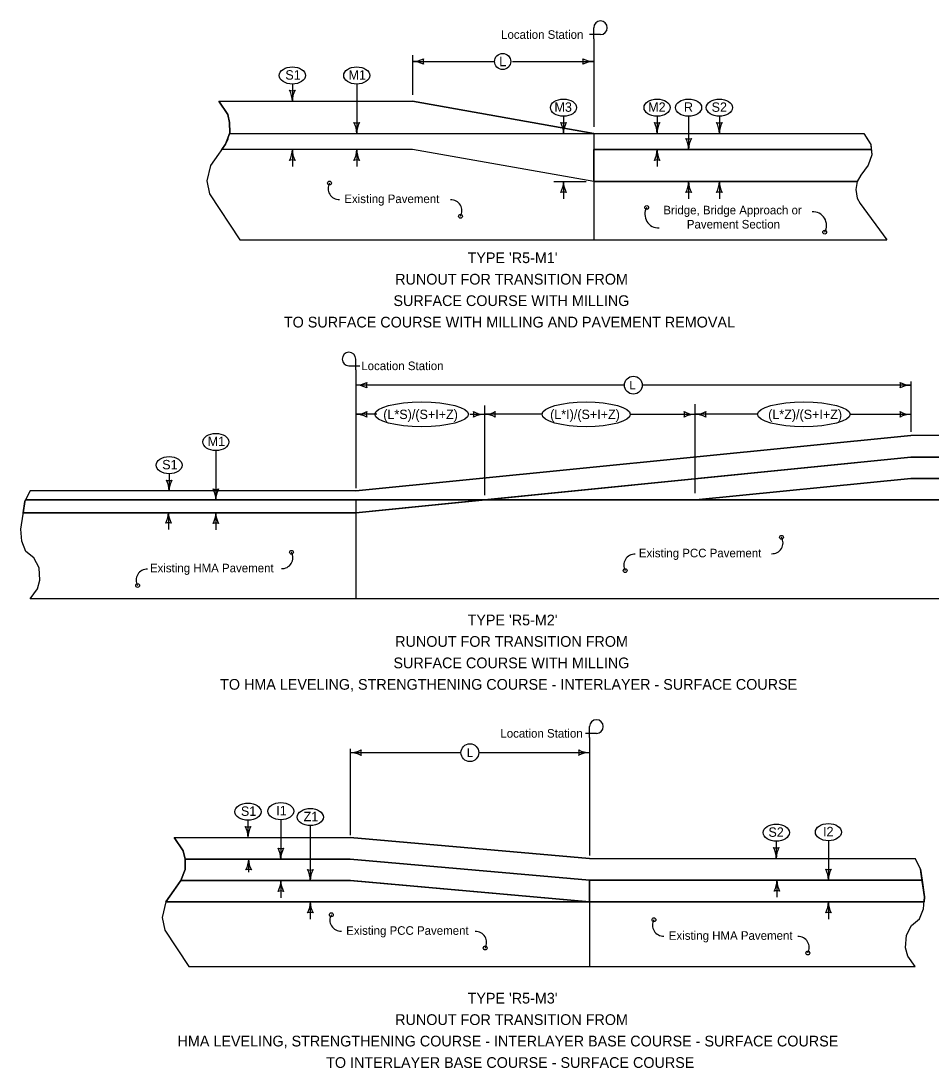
# Model space of a CAD drawing. Extents: x 10133 to 81668, y 2218 to 11018.
# Drawn here: x 10479 to 12176, y 5463 to 7415 of the extents above; entities that cross this region are included whole.
import ezdxf

# ---------------------------------------------------------------- set-up
doc = ezdxf.new("R2010")
doc.units = 0
for name, color, linetype in [('Default', 7, 'Continuous'), ('dsnNonPlotable', 7, 'Continuous'), ('dsnShtPlotShapeBatchPrint', 7, 'Continuous'), ('dsnStdBlock', 7, 'Continuous'), ('dsnStdBlockNotModified', 7, 'Continuous'), ('Level 2', 7, 'Continuous')]:
    doc.layers.add(name, color=color, linetype=linetype)

msp = doc.modelspace()

# ---------------------------------------------------------------- linework, layer by layer
at = {"layer": 'Default'}
for points in [[(10496.6, 6337.9), (10510.3, 6356.8), (10514.4, 6372.6), (10513, 6395.9), (10503.3, 6414.2), (10488.6, 6426.4), (10480.9, 6445.4), (10479.3, 6467.8), (10483.4, 6496), (10486.7, 6519.2), (10496.6, 6539.1)], [(12146.5, 5652.8), (12132.9, 5671.8), (12128.7, 5687.5), (12130.1, 5710.9), (12139.8, 5729.1), (12154.6, 5741.4), (12162.2, 5760.3), (12163.8, 5782.7), (12159.8, 5811), (12156.5, 5834.1), (12146.5, 5854.1)]]:
    msp.add_lwpolyline(points, dxfattribs=at)
at = {"layer": 'dsnNonPlotable'}
for points in [[(10860.9, 7185.7), (10868.7, 7206.5), (10868.4, 7225.7), (10865.1, 7241.1), (10848.4, 7265.7), (11209.6, 7265.7), (11547.1, 7205.7), (12050.8, 7205.7), (12057.2, 7195.4), (12063.6, 7185.2), (12064.6, 7175.7), (12065.6, 7165.6), (12058.6, 7146.2), (12045, 7127.7), (12038.3, 7115.7), (11547.1, 7115.7), (11209.6, 7175.7), (10853.8, 7175.7)], [(12446.5, 6601.8), (12449.8, 6617.8), (12466.5, 6642.4), (12138.6, 6642.4), (11103.6, 6539.1), (10496.6, 6539.1), (10486.7, 6519.2), (10483.7, 6498.5), (11103.6, 6498.5), (11343.4, 6522.4), (12138.6, 6601.8)], [(11343.4, 6522.4), (11737.8, 6522.4), (12138.6, 6562.4), (12454, 6562.4), (12446.2, 6583.3), (12446.5, 6601.8), (12138.6, 6601.8), (11343.4, 6522.4)], [(12242.3, 6521.8), (12482.2, 6522.4), (12467.4, 6543.7), (12454, 6562.4), (12138.6, 6562.4), (12138.6, 6562.4), (11737.8, 6522.4)], [(10781.9, 5868.2), (10765.2, 5892.8), (11093.1, 5892.8), (11539.6, 5854.1), (12146.5, 5854.1), (12156.5, 5834.1), (12159.4, 5813.4), (11539.6, 5813.4), (11093.1, 5852.8), (10785.2, 5852.8)], [(11539.6, 5813.4), (11539.6, 5772.8), (11093.5, 5812.8), (10777.7, 5812.8), (10785.5, 5833.6), (10785.2, 5852.8), (11093.1, 5852.8), (11539.6, 5813.4)], [(10749.5, 5772.8), (10764.3, 5794.1), (10777.7, 5812.8), (11093.1, 5812.8), (11539.6, 5772.8), (11539.6, 5772.8)], [(11539.6, 5813.4), (12159.4, 5813.4), (12163.8, 5782.7), (12163.1, 5772.8), (11539.6, 5772.8), (11539.6, 5813.4)]]:
    msp.add_lwpolyline(points, close=True, dxfattribs=at)
at = {"layer": 'dsnStdBlock'}
for p, q in [((11547.1, 7382.2), (11547.1, 7402.6)), ((11559.8, 7389.9), (11539.5, 7389.9)), ((11547.1, 7382.2), (11547.1, 7217.7)), ((11209.6, 7351.7), (11209.6, 7277.7)), ((11209.6, 7339.7), (11360.8, 7339.7)), ((11395.8, 7339.7), (11547.1, 7339.7)), ((10985.3, 7297.7), (10985.3, 7265.7)), ((11105.3, 7297.7), (11105.3, 7205.7)), ((10848.4, 7265.7), (11209.6, 7265.7)), ((11547.1, 7205.7), (11209.6, 7265.7)), ((11490.8, 7237.7), (11490.8, 7205.7)), ((11665.3, 7237.7), (11665.3, 7205.7)), ((11724.1, 7237.7), (11724.1, 7175.7)), ((11781.4, 7237.7), (11781.4, 7205.7)), ((10868, 7205.7), (11209.6, 7205.7)), ((11547.1, 7205.7), (11547.1, 7065.7)), ((11547.1, 7205.7), (12050.8, 7205.7)), ((11547.1, 7205.7), (11547.1, 7007.4)), ((11209.6, 7175.7), (10853.8, 7175.7)), ((10985.3, 7175.7), (10985.3, 7143.7)), ((11105.3, 7175.7), (11105.3, 7143.7)), ((11547.1, 7115.7), (11209.6, 7175.7)), ((12064.6, 7175.7), (11547.1, 7175.7)), ((11665.3, 7175.7), (11665.3, 7143.7)), ((11473.1, 7115.7), (11533.1, 7115.7)), ((11490.8, 7115.7), (11490.8, 7083.7)), ((11547.1, 7115.7), (12038.3, 7115.7)), ((11724.1, 7115.7), (11724.1, 7083.7)), ((11781.4, 7115.7), (11781.4, 7083.7)), ((10887.6, 7007.4), (12093.5, 7007.4)), ((11103.6, 6764.7), (11103.6, 6785)), ((11090.9, 6772.3), (11111.2, 6772.3)), ((11103.6, 6764.7), (11103.6, 6544.5)), ((11604.4, 6736.3), (11103.6, 6736.3)), ((12138.6, 6736.3), (11637.7, 6736.3)), ((12138.6, 6743.4), (12138.6, 6649.3)), ((11343.4, 6698.5), (11343.4, 6531.4)), ((11736, 6701.1), (11736, 6535.2)), ((11142.6, 6681.9), (11103.6, 6681.9)), ((11317.1, 6681.9), (11343.4, 6681.9)), ((11450.9, 6681.9), (11343.4, 6681.9)), ((11615.3, 6681.9), (11736, 6681.9)), ((11852.4, 6681.9), (11736, 6681.9)), ((12025, 6681.9), (12138.6, 6681.9)), ((11103.6, 6539.1), (12138.6, 6642.4)), ((12466.5, 6642.4), (12138.6, 6642.4)), ((10842.7, 6614.4), (10842.7, 6522.4)), ((11103.6, 6498.5), (12138.6, 6601.8)), ((12446.5, 6601.8), (12138.6, 6601.8)), ((10755.6, 6571.1), (10755.6, 6539.1)), ((11737.8, 6522.4), (12138.6, 6562.4)), ((12454, 6562.4), (12138.6, 6562.4)), ((12482.2, 6522.4), (10488.3, 6522.4)), ((11103.6, 6539.1), (10496.6, 6539.1)), ((11103.6, 6522.4), (11103.6, 6337.9)), ((11103.6, 6498.5), (10483.7, 6498.5)), ((10754.4, 6499.2), (10754.4, 6467.2)), ((10842.7, 6498.5), (10842.7, 6466.5)), ((12396.4, 6337.9), (10496.6, 6337.9)), ((11539.6, 6079.6), (11539.6, 6099.9)), ((11552.3, 6087.2), (11532, 6087.2)), ((11539.6, 6079.6), (11539.6, 5859.4)), ((11093.1, 6058.4), (11093.1, 5897.1)), ((11094.2, 6051.2), (11299.7, 6051.2)), ((11333, 6051.2), (11539.6, 6051.2)), ((10902.6, 5925.1), (10902.6, 5893.1)), ((10963.8, 5926.1), (10963.8, 5852.8)), ((11018.8, 5915.1), (11018.8, 5812.8)), ((10765.2, 5892.8), (11093.1, 5892.8)), ((11539.6, 5854.1), (11093.1, 5892.8)), ((11887.6, 5886.1), (11887.6, 5854.1)), ((11984.7, 5887.1), (11984.7, 5813.4)), ((10785.1, 5852.8), (11093.1, 5852.8)), ((10903.8, 5852.8), (10903.8, 5828.2)), ((11539.6, 5813.4), (11093.1, 5852.8)), ((11539.6, 5854.1), (12146.5, 5854.1)), ((10777.7, 5812.8), (11093.1, 5812.8)), ((10963.8, 5812.8), (10963.8, 5780.8)), ((11539.6, 5772.8), (11093.1, 5812.8)), ((11539.6, 5813.4), (12159.4, 5813.4)), ((11539.6, 5813.4), (11539.6, 5652.8)), ((11888.8, 5813.4), (11888.8, 5782.1)), ((10749.5, 5772.8), (12163.1, 5772.8)), ((11018.8, 5772.8), (11018.8, 5740.8)), ((11539.6, 5772.8), (11768.1, 5772.8)), ((11543.1, 5772.8), (12097.6, 5772.8)), ((11984.8, 5772.8), (11984.8, 5740.8)), ((10792.3, 5652.8), (12146.5, 5652.8))]:
    msp.add_line(p, q, dxfattribs=at)
for points in [[(10848.4, 7265.7), (10865.1, 7241.1), (10868.4, 7225.7), (10868.7, 7206.5), (10860.9, 7185.7), (10847.5, 7166.9), (10832.7, 7145.7), (10826.1, 7116.9), (10830.6, 7093), (10887.6, 7007.4)], [(10868, 7205.7), (11547.1, 7205.7), (12050.8, 7205.7), (12057.2, 7195.4), (12063.6, 7185.2), (12064.6, 7175.7), (11547.1, 7175.7), (11547.1, 7115.7), (11209.6, 7175.7), (10853.9, 7175.7), (10858.2, 7181.6), (10858.3, 7181.6)], [(12050.8, 7205.7), (12063.6, 7185.2), (12065.6, 7165.6), (12058.6, 7146.2), (12045, 7127.7), (12038.3, 7115.7), (12035.8, 7101.3), (12038.6, 7084.9), (12043.9, 7075.1), (12093.5, 7007.4)], [(10765.2, 5892.8), (10781.9, 5868.2), (10785.2, 5852.8), (10785.5, 5833.6), (10777.7, 5812.8), (10764.3, 5794.1), (10749.5, 5772.8), (10742.8, 5744.1), (10747.4, 5720.2), (10792.3, 5652.8)]]:
    msp.add_lwpolyline(points, dxfattribs=at)
for points in [[(11547.1, 7115.7), (11547.1, 7175.7), (12064.6, 7175.7), (12065.6, 7165.6), (12058.6, 7146.2), (12045, 7127.7), (12038.3, 7115.7)], [(10486.7, 6519.2), (10488.3, 6522.4), (11343.4, 6522.4), (11103.6, 6498.5), (10483.7, 6498.5)]]:
    msp.add_lwpolyline(points, close=True, dxfattribs=at)
for centre, radius in [((11377.4, 7339.7), 15), ((11054.6, 7113.1), 3.56), ((11646, 7067.6), 3.56), ((11298.9, 7051.1), 3.56), ((11977.8, 7021.4), 3.56), ((11621.1, 6736.3), 16.6), ((11897.4, 6452.7), 3.56), ((10983.7, 6424.8), 3.56), ((11605.9, 6390.6), 3.56), ((10696.8, 6362.7), 3.56), ((11316.3, 6051.2), 16.6), ((11058, 5749), 3.56), ((11659.5, 5739.7), 3.56), ((11344.8, 5687), 3.56), ((11946.3, 5677.7), 3.56)]:
    msp.add_circle(centre, radius, dxfattribs=at)
for centre, radius, start, end in [((11559.8, 7402.6), 12.7, 270, 180), ((11209.6, 7382.9), 43.2, 270, 298.0725), ((11245.8, 7339.7), 16.7, 162.2666, 197.7334), ((11510.9, 7339.7), 16.7, 342.2666, 17.7333), ((11547.1, 7382.9), 43.2, 241.9275, 270), ((11209.6, 7296.5), 43.2, 61.9275, 90), ((11547.1, 7296.5), 43.2, 90, 118.0725), ((10985.3, 7301.9), 16.7, 252.2666, 287.7333), ((10942.1, 7265.7), 43.2, 360, 28.0725), ((11028.4, 7265.7), 43.2, 151.9275, 180), ((11105.3, 7241.9), 16.7, 252.2666, 287.7333), ((11062.1, 7205.7), 43.2, 360, 28.0725), ((11148.4, 7205.7), 43.2, 151.9275, 180), ((11490.8, 7241.9), 16.7, 252.2666, 287.7333), ((11447.7, 7205.7), 43.2, 360, 28.0725), ((11534, 7205.7), 43.2, 151.9275, 180), ((11665.3, 7241.9), 16.7, 252.2666, 287.7333), ((11622.2, 7205.7), 43.2, 360, 28.0725), ((11708.5, 7205.7), 43.2, 151.9275, 180), ((11781.4, 7241.9), 16.7, 252.2666, 287.7333), ((11738.2, 7205.7), 43.2, 360, 28.0725), ((11824.6, 7205.7), 43.2, 151.9275, 180), ((11724.1, 7211.9), 16.7, 252.2666, 287.7333), ((11680.9, 7175.7), 43.2, 360, 28.0725), ((11767.3, 7175.7), 43.2, 151.9275, 180), ((10942.1, 7175.7), 43.2, 331.9275, 360), ((11028.4, 7175.7), 43.2, 180, 208.0725), ((11062.1, 7175.7), 43.2, 331.9275, 360), ((11148.4, 7175.7), 43.2, 180, 208.0725), ((11622.2, 7175.7), 43.2, 331.9275, 360), ((11708.5, 7175.7), 43.2, 180, 208.0725), ((10985.3, 7139.5), 16.7, 72.2666, 107.7334), ((11105.3, 7139.5), 16.7, 72.2666, 107.7334), ((11665.3, 7139.5), 16.7, 72.2666, 107.7334), ((11072.3, 7102.9), 20.4, 150.0683, 272.8436), ((11447.7, 7115.7), 43.2, 331.9275, 360), ((11534, 7115.7), 43.2, 180, 208.0725), ((11680.9, 7115.7), 43.2, 331.9275, 360), ((11767.3, 7115.7), 43.2, 180, 208.0725), ((11738.2, 7115.7), 43.2, 331.9275, 360), ((11824.6, 7115.7), 43.2, 180, 208.0725), ((11490.8, 7079.5), 16.7, 72.2666, 107.7334), ((11724.1, 7079.5), 16.7, 72.2666, 107.7334), ((11781.4, 7079.5), 16.7, 72.2666, 107.7334), ((11281.2, 7061.3), 20.4, 330.0683, 92.8436), ((11668.2, 7054.9), 25.6, 150.0683, 272.8436), ((11955.6, 7034.1), 25.6, 330.0683, 92.8436), ((11090.9, 6785), 12.7, 0, 270), ((11103.6, 6779.5), 43.2, 270, 298.0725), ((11103.6, 6693.1), 43.2, 61.9275, 90), ((11139.8, 6736.3), 16.7, 162.2666, 197.7334), ((12102.4, 6736.2), 16.7, 342.2667, 17.7334), ((12138.6, 6779.4), 43.2, 241.9275, 270), ((12138.6, 6693), 43.2, 90, 118.0725), ((11103.6, 6725), 43.2, 270, 298.0725), ((11103.6, 6638.7), 43.2, 61.9275, 90), ((11139.8, 6681.9), 16.7, 162.2666, 197.7334), ((11307.2, 6681.9), 16.7, 342.2667, 17.7334), ((11343.4, 6725), 43.2, 241.9275, 270), ((11343.4, 6638.7), 43.2, 90, 118.0725), ((11343.4, 6725), 43.2, 270, 298.0725), ((11343.4, 6638.7), 43.2, 61.9275, 90), ((11379.6, 6681.9), 16.7, 162.2666, 197.7334), ((11699.8, 6681.9), 16.7, 342.2667, 17.7334), ((11736, 6725), 43.2, 241.9275, 270), ((11736, 6638.7), 43.2, 90, 118.0725), ((11736, 6725), 43.2, 270, 298.0725), ((11736, 6638.7), 43.2, 61.9275, 90), ((11772.2, 6681.9), 16.7, 162.2666, 197.7334), ((12102.4, 6681.9), 16.7, 342.2667, 17.7334), ((12138.6, 6725), 43.2, 241.9275, 270), ((12138.6, 6638.7), 43.2, 90, 118.0725), ((10755.6, 6575.3), 16.7, 252.2666, 287.7334), ((10712.4, 6539.1), 43.2, 0, 28.0725), ((10798.8, 6539.1), 43.2, 151.9275, 180), ((10842.7, 6558.6), 16.7, 252.2666, 287.7333), ((10799.5, 6522.4), 43.2, 360, 28.0725), ((10885.8, 6522.4), 43.2, 151.9275, 180), ((10711.2, 6499.2), 43.2, 331.9275, 0), ((10797.6, 6499.2), 43.2, 180, 208.0725), ((10799.5, 6498.5), 43.2, 331.9275, 360), ((10885.8, 6498.5), 43.2, 180, 208.0725), ((10754.4, 6463), 16.7, 72.2666, 107.7334), ((10842.7, 6462.3), 16.7, 72.2666, 107.7334), ((11879.7, 6442.5), 20.4, 267.1564, 29.9317), ((10965.9, 6414.6), 20.4, 267.1564, 29.9317), ((11623.7, 6400.8), 20.4, 87.1564, 209.9317), ((10714.5, 6372.9), 20.4, 87.1564, 209.9317), ((11552.3, 6099.9), 12.7, 270, 180), ((11093.1, 6094.4), 43.2, 270, 298.0725), ((11129.3, 6051.2), 16.7, 162.2666, 197.7334), ((11503.4, 6051.2), 16.7, 342.2666, 17.7333), ((11539.6, 6094.4), 43.2, 241.9275, 270), ((11093.1, 6008), 43.2, 61.9275, 90), ((11539.6, 6008.1), 43.2, 90, 118.0725), ((10902.6, 5929.4), 16.7, 252.2666, 287.7333), ((10859.5, 5893.1), 43.2, 360, 28.0725), ((10945.8, 5893.1), 43.2, 151.9275, 180), ((10963.8, 5889), 16.7, 252.2666, 287.7333), ((10920.6, 5852.8), 43.2, 360, 28.0725), ((11007, 5852.8), 43.2, 151.9275, 180), ((11887.6, 5890.3), 16.7, 252.2666, 287.7333), ((11844.4, 5854.1), 43.2, 360, 28.0725), ((11930.7, 5854.1), 43.2, 151.9275, 180), ((10860.7, 5852.8), 43.2, 331.9275, 360), ((10947, 5852.8), 43.2, 180, 208.0725), ((10903.8, 5816.6), 16.7, 72.2666, 107.7334), ((11018.8, 5849), 16.7, 252.2666, 287.7333), ((10975.6, 5812.8), 43.2, 360, 28.0725), ((11062, 5812.8), 43.2, 151.9275, 180), ((11984.8, 5850), 16.7, 252.2666, 287.7333), ((11941.6, 5813.8), 43.2, 360, 28.0725), ((12028, 5813.8), 43.2, 151.9275, 180), ((10920.7, 5812.8), 43.2, 331.9275, 360), ((11007, 5812.8), 43.2, 180, 208.0725), ((11845.6, 5813.4), 43.2, 331.9275, 360), ((11931.9, 5813.4), 43.2, 180, 208.0725), ((10963.8, 5776.6), 16.7, 72.2666, 107.7334), ((11888.8, 5777.2), 16.7, 72.2666, 107.7334), ((10975.7, 5772.8), 43.2, 331.9275, 360), ((11062, 5772.8), 43.2, 180, 208.0725), ((11941.6, 5772.8), 43.2, 331.9275, 360), ((12028, 5772.8), 43.2, 180, 208.0725), ((11018.8, 5736.6), 16.7, 72.2666, 107.7334), ((11075.7, 5738.8), 20.4, 150.0683, 272.8436), ((11677.2, 5729.5), 20.4, 150.0683, 272.8436), ((11984.8, 5736.6), 16.7, 72.2666, 107.7334), ((11327.1, 5697.2), 20.4, 330.0683, 92.8436), ((11928.6, 5687.9), 20.4, 330.0683, 92.8436)]:
    msp.add_arc(centre, radius, start, end, dxfattribs=at)
for centre, major_axis, ratio in [((10985.3, 7313.7), (24.3, 0), 0.658717), ((11105.3, 7313.7), (-24.3, 0), 0.658717), ((11490.8, 7253.7), (-24.3, 0), 0.658717), ((11665.3, 7253.7), (-24.3, 0), 0.658717), ((11724.1, 7253.7), (24.3, 0), 0.658717), ((11781.4, 7253.7), (24.3, 0), 0.658717), ((11226.6, 6681.9), (-87.3, 0), 0.264007), ((11533.1, 6681.9), (-82.2, 0), 0.280198), ((11938.7, 6681.9), (-86.3, 0), 0.266932), ((10842.7, 6630.4), (-24.3, 0), 0.658717), ((10755.6, 6587.1), (24.3, 0), 0.658717), ((10902.6, 5941.1), (-24.3, 0), 0.658717), ((10963.8, 5942.1), (-24.3, 0), 0.658717), ((11018.8, 5931.1), (-24.3, 0), 0.658717), ((11887.6, 5902.1), (-24.3, 0), 0.658717), ((11984.7, 5903.1), (-24.3, 0), 0.658717)]:
    msp.add_ellipse(centre, major_axis=major_axis, ratio=ratio, dxfattribs=at)
msp.add_ellipse((10832.3, 7216.9), major_axis=(0, -50), ratio=0.732645, start_param=0.785398, end_param=1.343633, dxfattribs=at)

# ---------------------------------------------------------------- texts
at = {"layer": 'dsnShtPlotShapeBatchPrint'}
for s, p in [('(L*S)/(S+I+Z)', (11154.8, 6673.1)), ('(L*I)/(S+I+Z)', (11465.9, 6673.1)), ('(L*Z)/(S+I+Z)', (11872.4, 6673.1))]:
    msp.add_text(s, height=17.5, dxfattribs=at).set_placement(p)
at = {"layer": 'dsnStdBlockNotModified'}
for s, height, p in [('Location Station', 16, (11374.5, 7381.9)), ('L', 17.5, (11371.1, 7330.9)), ('S1', 17.5, (10972.3, 7305.9)), ('M1', 17.5, (11090.1, 7305.9)), ('M3', 17.5, (11474, 7245.9)), ('M2', 17.5, (11648.7, 7245.9)), ('R', 17.5, (11715.4, 7245.9)), ('S2', 17.5, (11767, 7245.9)), ('Existing Pavement', 16, (11082.2, 7075.7)), ('Bridge, Bridge Approach or', 16, (11677, 7054.7)), ('Pavement Section', 16, (11720.8, 7028.3)), ("TYPE 'R5-M1'", 20, (11312, 6963.8)), ('RUNOUT FOR TRANSITION FROM', 20, (11177.1, 6923.8)), ('SURFACE COURSE WITH MILLING', 20, (11173.8, 6883.8)), ('TO SURFACE COURSE WITH MILLING AND PAVEMENT REMOVAL', 20, (10969.5, 6843.8)), ('Location Station', 16, (11113.8, 6764.3)), ('L', 15.8, (11613.6, 6728.4)), ('M1', 17.5, (10827.5, 6622.7)), ('S1', 17.5, (10742.7, 6579.4)), ('Existing PCC Pavement', 16, (11631.4, 6415.3)), ('Existing HMA Pavement', 16, (10719.8, 6387.4)), ('Location Station', 16, (11373.2, 6079.2)), ('L', 15.8, (11310.7, 6043.4)), ('S1', 17.5, (10889.4, 5933.4)), ('I1', 17.5, (10955.2, 5934.4)), ('Z1', 17.5, (11006.3, 5923.4)), ('S2', 17.5, (11872.9, 5894.3)), ('I2', 17.5, (11974.7, 5895.3)), ('Existing PCC Pavement', 16, (11085.7, 5711.6)), ('Existing HMA Pavement', 16, (11687.2, 5702.3))]:
    msp.add_text(s, height=height, dxfattribs=at).set_placement(p)
at = {"layer": 'Level 2'}
for s, p in [("TYPE 'R5-M2'", (11312, 6288.5)), ('RUNOUT FOR TRANSITION FROM', (11177.1, 6248.5)), ('SURFACE COURSE WITH MILLING', (11173.8, 6208.5)), ('TO HMA LEVELING, STRENGTHENING COURSE - INTERLAYER - SURFACE COURSE', (10850.6, 6168.5)), ("TYPE 'R5-M3'", (11312, 5583.5)), ('RUNOUT FOR TRANSITION FROM', (11177.1, 5543.5)), ('HMA LEVELING, STRENGTHENING COURSE - INTERLAYER BASE COURSE - SURFACE COURSE', (10771.3, 5503.5)), ('TO INTERLAYER BASE COURSE - SURFACE COURSE', (11048.3, 5463.5))]:
    msp.add_text(s, height=20, dxfattribs=at).set_placement(p)

doc.saveas('drawing.dxf')
